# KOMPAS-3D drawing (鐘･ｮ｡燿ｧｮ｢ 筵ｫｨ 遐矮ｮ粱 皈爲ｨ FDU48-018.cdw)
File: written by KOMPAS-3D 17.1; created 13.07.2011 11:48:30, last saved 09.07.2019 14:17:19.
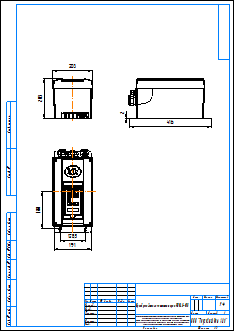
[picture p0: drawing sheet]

Title block, sheet 1: name: Преобразователи частоты серии FDU48-018; scale: 1:4; sheets: 1; sheet format: A3; stored path: \\adlc.lan\data\АДЛ_ПКД\3D-модели\Поставщики\Оборудование Emotron\Преобразователи частоты\Серия FDU 2.0\KOMPAS 2D\Преобразователи частоты серии FDU48-018.cdw

Views: Спереди 1
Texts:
  Рама для чертежей
  Лит-Масса-Масштаб
  Материал-Предприятие
  Масштаб
  Изм.
  Лист
  № докум.
  Подп.
  Дата
  Лит.
  Разраб.
  Пров.
  Т.контр.
  Листов
  Внимание! Данный продукт является объектом авторского права ООО «Торговый Дом АДЛ».
  Запрещается изменение, копирование, распространение
  (в том числе путем копирования на другие сайты и ресурсы в Интернете)
  или любое иное использование информации и объектов без предварительного
  согласия правообладателя (ООО «Торговый Дом АДЛ»).
  Н.контр.
  Утв.
  ООО "Торговый дом АДЛ"
  Изменение
  Номер документа
  Подпись
  Обозначение документа
  Наименование изделия
  Масса изделия по ГОСТ 2.109-73
  Порядковый номер листа
  Общее количество листов в документе
  Характер работы, выполненной лицом, подписавшим документ
  Наименование или индекс предприятия, выпускающего документ
  Инв. № подл.
  Подп. и дата
  Взам. инв. №
  Инв. № дубл.
  Инвентарный номер подлинника по ГОСТ 2.501-68
  Подпись принявшего подлинник в отдел технической документации
  Инвентарный номер подлинника, взамен которого выпущен данный подлинник
  Инвентарный номер дубликата по ГОСТ 2.502-68
  Подпись принявшего дубликат в отдел технической документации
  Справ. №
  Перв. примен.
  Обозначение документа, взамен или на основании которого выпущен данный документ
  Обозначение документа, в котором впервые записан данный документ
  Подпись лица, копировавшего чертеж
  Обозначение формата листа
  !Рама для чертежа
Dimensions and other numbers on the sheet: 203; 128,5; 191; 416; 2; 188; 1:4; 1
